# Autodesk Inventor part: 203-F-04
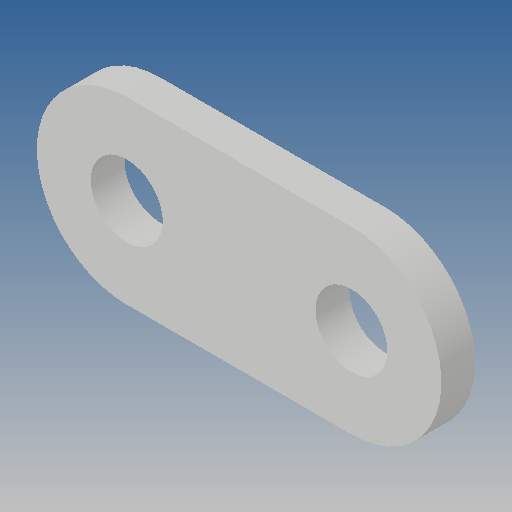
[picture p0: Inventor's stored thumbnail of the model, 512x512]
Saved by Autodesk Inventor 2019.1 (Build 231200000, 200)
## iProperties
Created: 2012-09
Part Number: 203-F-04
Material: Ogólny
Document SubType Name: Modeling
Designer: CADENGINEERING4
Density: 1 g/cm^3
Appearance: Domyślna
Author: CADENGINEERING4
Revision Number: ÈÎºÎ
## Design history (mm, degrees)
feature "À­Éì1"
node "Bryła1"
